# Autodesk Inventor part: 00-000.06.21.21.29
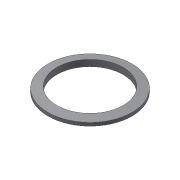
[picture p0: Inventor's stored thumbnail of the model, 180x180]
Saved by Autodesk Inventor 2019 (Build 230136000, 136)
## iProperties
Created: 2019-01
Part Number: 00-000.06.21.21.29
Material: Rubber
Document SubType Name: Modeling
Designer: m.vorobev
Density: 0.93 g/cm^3
Appearance: Rubber - Black
Author: m.vorobev
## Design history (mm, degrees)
sketch "Sketch1"
  geometry: L1 (26, 3.544)-(34.5, 2.5); L2 (34.5, 2.5)-(34.5, -2.5); L3 (34.5, -2.5)-(26, -3.544); L4 (26, -3.544)-(26, 3.544); L5 (26, 0)-(34.5, 0); L6 (0, 0)-(0, 8.449); 1 further point
  constraints: 12 end point, 3 midpoint, 2 vertical, 1 horizontal, 1 horizontal alignment, 1 parallel
  dimensions: "d1" = 52 diameter of L4 L6; "d2" = 69 diameter of L2 L6; "d3" = 14 deg angle of L3 L1; "d4" = 5 distance of L1.end L2.end
revolve "Revolution1" sketch "Sketch1" stored, may be unused: angle "d0" = 90 deg
body "Solid1"
